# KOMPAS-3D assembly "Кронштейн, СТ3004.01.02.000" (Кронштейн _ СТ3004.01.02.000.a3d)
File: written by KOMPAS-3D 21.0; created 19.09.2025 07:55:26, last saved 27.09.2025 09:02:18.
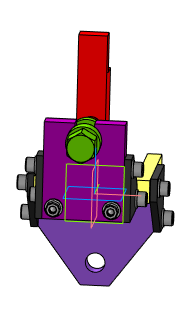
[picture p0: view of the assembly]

Document properties: Полное имя файла: C:\Users\Lutik\Yandex.Disk\Документы\Новая папка\Стапель №2\Стапель _ СТ3004.00.00.000\Опора _ СТ3004.01.00.000\3D\Кронштейн _ СТ3004.01.02.000\Кронштейн _ СТ3004.01.02.000.a3d; Автор: 1

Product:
- Part/product: Кронштейн  | designation СТ3004.01.02.000
    Масса: 5.184451
    Форматы листов документа: A3
  - Component [detail]: Направляющая  | designation СТ3004.01.02.001  | pos. 5  | Материал: Сталь 45  ГОСТ 1050-2013 (density 7810 kg/m3); Масса: 1.713262; Форматы листов документа: A3; source file: ..\..\2D\Кронштейн _ СТ3004.01.02.000\Направляющая _ СТ3004.01.02.001.cdw, Направляющая _ СТ3004.01.02.001.m3d
  - Component [detail]: Упор  | designation СТ3004.01.02.002  | pos. 6  | Материал: Сталь 45  ГОСТ 1050-2013 (density 7810 kg/m3); Масса: 1.036373; Форматы листов документа: A3; source file: ..\..\2D\Кронштейн _ СТ3004.01.02.000\Упор _ СТ3004.01.02.002.cdw, Упор _ СТ3004.01.02.002.m3d
  - Component [detail]: Пластина  | designation СТ3003.01.02.002  | pos. 4  | Материал: Лист$dБ-ПН-НО-16 ГОСТ 19903-2015;Ст3сп ГОСТ 14637-89$ (density 7850 kg/m3); Масса: 0.780129; Форматы листов документа: A3; source file: ..\..\..\..\Стапель _ СТ3003.00.00.000\Опора _ СТ3003.01.00.000\3D\Кронштейн _ СТ3003.01.02.000\Пластина _ СТ3003.01.02.002.m3d
  - Component [detail]: Косынка  | designation СТ3003.01.01.002  | qty 4  | pos. 2  | Материал: Лист$dБ-ПН-НО-6 ГОСТ 19903-2015;Ст3сп ГОСТ 14637-89$ (density 7850 kg/m3); Масса: 0.116828; Форматы листов документа: A4; source file: ..\..\..\..\Стапель _ СТ3003.00.00.000\Опора _ СТ3003.01.00.000\3D\Кронштейн _ СТ3003.01.01.000\Косынка _ СТ3003.01.01.002.m3d
  - Component [detail]: Винт  | designation СТ3003.01.01.001  | pos. 1  | Материал: Круг$d30 ГОСТ 2590-2006;Ст3сп ГОСТ 535-2005$ (density 7850 kg/m3); Масса: 0.311599; Форматы листов документа: A4; additional columns: 110; source file: ..\..\..\..\Стапель _ СТ3003.00.00.000\Опора _ СТ3003.01.00.000\2D\Кронштейн _ СТ3003.01.01.000\Винт _ СТ3003.01.01.001.cdw, ..\..\..\..\Стапель _ СТ3003.00.00.000\Опора _ СТ3003.01.00.000\3D\Кронштейн _ СТ3003.01.01.000\Винт _ СТ3003.01.01.001.m3d
  - Component [detail]: Пластина  | designation СТ3003.01.01.006  | pos. 3  | Материал: Лист$dБ-ПН-НО-16 ГОСТ 19903-2015;Ст3сп ГОСТ 14637-89$ (density 7850 kg/m3); Масса: 0.669577; Форматы листов документа: A4; source file: ..\..\..\..\Стапель _ СТ3003.00.00.000\Опора _ СТ3003.01.00.000\3D\Кронштейн _ СТ3003.01.01.000\Пластина _ СТ3003.01.01.006.m3d
  - Component [standard]: Шайба A.8.01.10.019 ГОСТ 11371-78  | qty 10  | pos. 9  | Масса: 0.001828; Раздел спецификации: Стандартные изделия; Рассекать на разрезах: no
  - Component [standard]: Винт М8-6gx25.56.019 ГОСТ 11738-84  | qty 10  | pos. 7  | Материал: Сталь 30 ГОСТ 1050-2013 (density 1000 kg/m3); Масса: 0.01513; Раздел спецификации: Стандартные изделия; Рассекать на разрезах: no
  - Component [standard]: Винт М8-6gx35.56.019 ГОСТ 11738-84  | qty 2  | pos. 8  | Материал: Сталь 30 ГОСТ 1050-2013 (density 1000 kg/m3); Масса: 0.01831; Раздел спецификации: Стандартные изделия; Рассекать на разрезах: no

Referenced files in C:\Users\Lutik\Yandex.Disk\Документы\Новая папка\Стапель №2\Стапель _ СТ3004.00.00.000\Опора _ СТ3004.01.00.000\3D\Кронштейн _ СТ3004.01.02.000\: Направляющая _ СТ3004.01.02.001.m3d, Упор _ СТ3004.01.02.002.m3d
Referenced files in C:\Users\1\Yandex.Disk\Документы\Новая папка\Стапель №2\Стапель _ СТ3003.00.00.000\Опора _ СТ3003.01.00.000\3D\Кронштейн _ СТ3003.01.02.000\: Пластина _ СТ3003.01.02.002.m3d
Referenced files in C:\Users\1\Yandex.Disk\Документы\Новая папка\Стапель №2\Стапель _ СТ3003.00.00.000\Опора _ СТ3003.01.00.000\3D\Кронштейн _ СТ3003.01.01.000\: Косынка _ СТ3003.01.01.002.m3d, Винт _ СТ3003.01.01.001.m3d, Пластина _ СТ3003.01.01.006.m3d
Referenced files in C:\Users\Lutik\Yandex.Disk\Документы\Новая папка\Стапель №2\Стапель _ СТ3004.00.00.000\Опора _ СТ3004.01.00.000\2D\Кронштейн _ СТ3004.01.02.000\: Направляющая _ СТ3004.01.02.001.cdw, Упор _ СТ3004.01.02.002.cdw
Referenced files in C:\Users\Lutik\Yandex.Disk\Документы\Новая папка\Стапель №2\Стапель _ СТ3003.00.00.000\Опора _ СТ3003.01.00.000\3D\Кронштейн _ СТ3003.01.02.000\: Пластина _ СТ3003.01.02.002.m3d
Referenced files in C:\Users\Lutik\Yandex.Disk\Документы\Новая папка\Стапель №2\Стапель _ СТ3003.00.00.000\Опора _ СТ3003.01.00.000\3D\Кронштейн _ СТ3003.01.01.000\: Косынка _ СТ3003.01.01.002.m3d, Винт _ СТ3003.01.01.001.m3d, Пластина _ СТ3003.01.01.006.m3d
Referenced files in C:\Users\Lutik\Yandex.Disk\Документы\Новая папка\Стапель №2\Стапель _ СТ3003.00.00.000\Опора _ СТ3003.01.00.000\2D\Кронштейн _ СТ3003.01.01.000\: Винт _ СТ3003.01.01.001.cdw
Referenced files in C:\Program Files\ASCON\KOMPAS-3D v21\Libs\PARTLib\DATA\vault\Methods\Kompas\3D\: PLib_Washer_1_712.m3d
Referenced files in C:\Program Files\ASCON\KOMPAS-3D v21\Libs\PartLib\DATA\VAULT\Methods\Kompas\3D\: PLib_Screw_GOST_11738_1500.m3d
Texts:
  СТ3004.01.02.001
  СТ3003.01.02.002
  СТ3003.01.01.002
  СТ3004.01.02.002
  СТ3003.01.01.001
  СТ3003.01.01.006
  Крепежное изделие ГОСТ
  СТ3004.01.02.000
